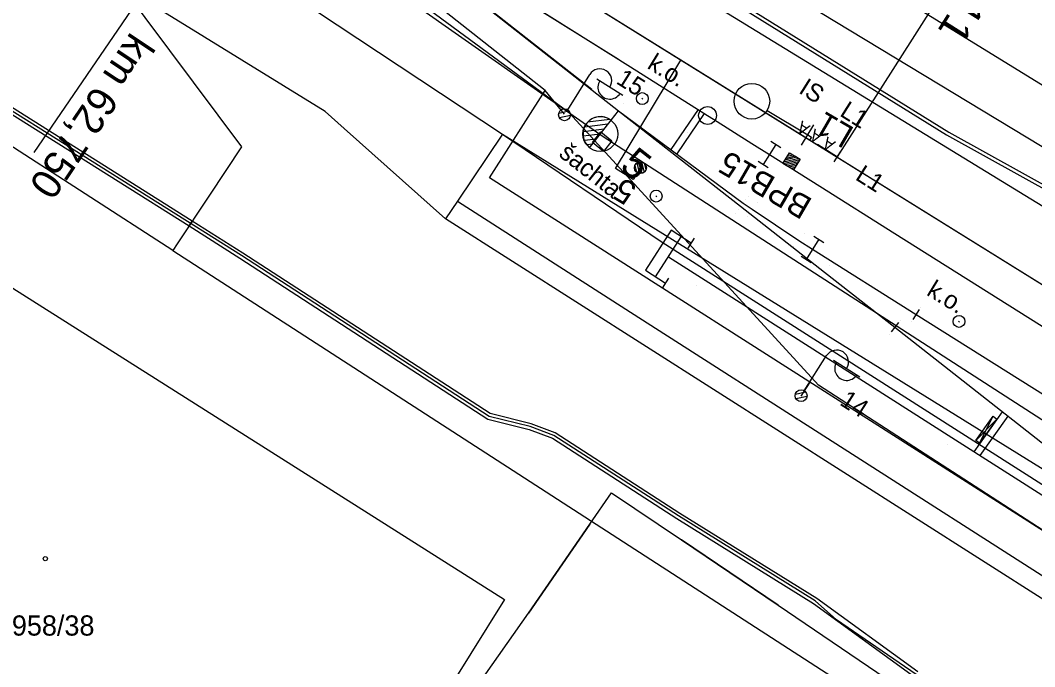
# Model space of a CAD drawing. Extents: x -621168 to -620292, y -1122748 to -1122069.
# Drawn here: x -620861.7 to -620776.3, y -1122403.6 to -1122349.2 of the extents above; entities that cross this region are included whole.
import ezdxf

# ---------------------------------------------------------------- set-up
doc = ezdxf.new("R2010")
doc.units = 0
for name, color, linetype in [('060601_EOV', 7, 'Continuous'), ('060604_ROZVODY_SEE', 7, 'Continuous'), ('CETIN', 7, 'Continuous'), ('HranDP', 7, 'Continuous'), ('Hranice parcel', 7, 'Continuous'), ('itself', 7, 'Continuous'), ('Parcelní čísla', 7, 'Continuous'), ('PS 06-14-01_trasa_sdělovací_nové', 7, 'Continuous'), ('SEE', 7, 'Continuous'), ('SSZT', 7, 'Continuous'), ('SSZT-DK', 7, 'Continuous'), ('UZEMNĚNÍ', 7, 'Continuous'), ('Vnitřní kresba', 7, 'Continuous'), ('Vrstva 1', 7, 'Continuous'), ('Vrstva 10', 7, 'Continuous'), ('Vrstva 15', 7, 'Continuous'), ('Vrstva 2', 7, 'Continuous'), ('Vrstva 25', 7, 'Continuous'), ('Vrstva 27', 7, 'Continuous'), ('Vrstva 3', 7, 'Continuous'), ('Vrstva 47', 7, 'Continuous'), ('Vrstva 6', 7, 'Continuous'), ('Vrstva 62', 7, 'Continuous'), ('Vrstva 7', 7, 'Continuous'), ('Věcná břemena k části', 7, 'Continuous'), ('Značky budov', 7, 'Continuous'), ('ČD-T', 7, 'Continuous')]:
    doc.layers.add(name, color=color, linetype=linetype)

msp = doc.modelspace()

# ---------------------------------------------------------------- linework, layer by layer
at = {"layer": '060601_EOV'}
msp.add_lwpolyline([(-620377.179, -1122637.257), (-620411.557, -1122614.916), (-620424.156, -1122607.087), (-620443.525, -1122595.005), (-620456.111, -1122587.123), (-620447.823, -1122572.959), (-620450.948, -1122571.455), (-620470.592, -1122561.479), (-620499.61, -1122545.574), (-620522.038, -1122531.471), (-620538.89, -1122521.208), (-620599.215, -1122483.216), (-620683.524, -1122429.444), (-620729.121, -1122400.659), (-620738.886, -1122415.694), (-620750.529, -1122408.246), (-620763.558, -1122399.82), (-620784.65, -1122386.386), (-620822.218, -1122362.419), (-620817.53, -1122355.085), (-620826.407, -1122348.082), (-620839.916, -1122337.943), (-620848.842, -1122331.997), (-620848.834, -1122331.986)], dxfattribs=at)
at = {"layer": '060604_ROZVODY_SEE'}
for p, q in [((-620815.893, -1122357.078), (-620817.53, -1122355.085)), ((-620795.983, -1122380.803), (-620795.236, -1122379.632))]:
    msp.add_line(p, q, dxfattribs=at)
msp.add_lwpolyline([(-620443.525, -1122595.005), (-620456.111, -1122587.123), (-620447.823, -1122572.959), (-620450.948, -1122571.455), (-620470.592, -1122561.479), (-620499.61, -1122545.574), (-620522.038, -1122531.471), (-620538.89, -1122521.208), (-620599.215, -1122483.216), (-620683.524, -1122429.444), (-620729.121, -1122400.659), (-620738.886, -1122415.694), (-620750.529, -1122408.246), (-620763.558, -1122399.82), (-620784.65, -1122386.386), (-620822.218, -1122362.419), (-620817.53, -1122355.085), (-620826.407, -1122348.082), (-620839.916, -1122337.943), (-620854.567, -1122328.184), (-620868.06, -1122319.694), (-620885.37, -1122308.815), (-620912.868, -1122291.527), (-620913.325, -1122292.255)], dxfattribs=at)
at = {"layer": 'CETIN'}
for points in [[(-621086.886, -1122186.715), (-621044.703, -1122204.841), (-620975.938, -1122239.692), (-620943.103, -1122258.616), (-620748.436, -1122376.269), (-620484.52, -1122538.147)], [(-620825.92, -1122405.87), (-620824.51, -1122406.99), (-620818.94, -1122399.06), (-620813.77, -1122391.56), (-620811.94, -1122388.94), (-620806.05, -1122392.88), (-620797.93, -1122398.39), (-620788.82, -1122404.57), (-620785.51, -1122405.86), (-620781.04, -1122408.44), (-620779.59, -1122408.85), (-620776.1, -1122410.97), (-620774.86, -1122411.81), (-620766.93, -1122416.76), (-620729.54, -1122440.11), (-620722.4, -1122445), (-620713.88, -1122450.37)], [(-620813.77, -1122391.56), (-620818.94, -1122399.06)], [(-620797.93, -1122398.39), (-620806.05, -1122392.88)]]:
    msp.add_lwpolyline(points, dxfattribs=at)
at = {"layer": 'HranDP'}
msp.add_line((-620856.79, -1122335.14), (-620821.12, -1122358.76), dxfattribs=at)
for points in [[(-620847.72, -1122320.67), (-620838.83, -1122326.12), (-620768.63, -1122369.09), (-620748.53, -1122378.52), (-620702.13, -1122406.7), (-620691.02, -1122413.66), (-620638.48, -1122446.57), (-620552.09, -1122499.2)], [(-620821.12, -1122358.76), (-620741.46, -1122408.09), (-620679.51, -1122447.56), (-620545.92, -1122532.26), (-620521.41, -1122548.27), (-620511.29, -1122557.64)]]:
    msp.add_lwpolyline(points, dxfattribs=at)
at = {"layer": 'Hranice parcel'}
for p, q in [((-620866.03, -1122298.98), (-620688.16, -1122408.5)), ((-620848.87, -1122368.55), (-620933.94, -1122313.6)), ((-620856.79, -1122335.14), (-620821.12, -1122358.76))]:
    msp.add_line(p, q, dxfattribs=at)
for points in [[(-620847.72, -1122320.67), (-620838.83, -1122326.12), (-620768.63, -1122369.09), (-620748.53, -1122378.52), (-620702.13, -1122406.7), (-620691.02, -1122413.66), (-620638.48, -1122446.57), (-620552.09, -1122499.2)], [(-620825.92, -1122365.89), (-620834.44, -1122358.28), (-620836.04, -1122356.85), (-620853.22, -1122346.25)], [(-620853.22, -1122346.25), (-620843.09, -1122359.81), (-620845.8, -1122363.88), (-620848.5, -1122367.99), (-620848.87, -1122368.55)], [(-620929.94, -1122378.34), (-620913.46, -1122352.29), (-620887.98, -1122368.3), (-620877.81, -1122374.71), (-620872.17, -1122365.51), (-620820.94, -1122397.9), (-620826.62, -1122407), (-620821.36, -1122410.31), (-620837.94, -1122436.41), (-620904.18, -1122394.6), (-620929.94, -1122378.34)], [(-620821.12, -1122358.76), (-620824.91, -1122364.39), (-620825.92, -1122365.89)], [(-620821.12, -1122358.76), (-620741.46, -1122408.09), (-620679.51, -1122447.56), (-620545.92, -1122532.26), (-620521.41, -1122548.27), (-620511.29, -1122557.64)], [(-620821.12, -1122358.76), (-620807.67, -1122367.84), (-620645.72, -1122471.03), (-620587.17, -1122509.18), (-620511.29, -1122557.64)], [(-620557.45, -1122536.96), (-620684.91, -1122455.63), (-620825.92, -1122365.89)], [(-620848.87, -1122368.55), (-620781.81, -1122411.87), (-620814.37, -1122462.27), (-620846.855, -1122512.555)]]:
    msp.add_lwpolyline(points, dxfattribs=at)
at = {"layer": 'itself'}
msp.add_lwpolyline([(-620786.306, -1122404.212), (-620792.996, -1122399.612), (-620794.806, -1122398.032), (-620806.306, -1122390.882), (-620816.806, -1122384.122), (-620818.796, -1122383.362), (-620822.246, -1122382.502), (-620843.096, -1122368.972), (-620871.286, -1122351.222)], dxfattribs=at)
at = {"layer": 'PS 06-14-01_trasa_sdělovací_nové'}
msp.add_lwpolyline([(-620756.33, -1122383.523), (-620759.752, -1122381.362), (-620756.353, -1122375.206), (-620764.724, -1122371.2), (-620767.847, -1122376.3), (-620853.066, -1122323.342), (-620895.691, -1122296.632), (-620912.11, -1122286.226), (-620914.885, -1122290.617), (-620964.537, -1122259.534), (-620982.106, -1122249.221), (-620983.24, -1122251.5), (-621017.63, -1122231.729), (-621052.339, -1122216.079), (-621085.519, -1122202.489), (-621084.026, -1122198.756), (-621092.027, -1122195.557)], dxfattribs=at)
at = {"layer": 'SEE'}
msp.add_lwpolyline([(-620377.188, -1122637.273), (-620390.254, -1122629.02), (-620411.934, -1122614.961), (-620423.125, -1122608.012), (-620468.337, -1122579.91), (-620468.337, -1122579.91), (-620460.94, -1122568.103), (-620517.418, -1122533.032), (-620535.001, -1122522.477), (-620545.407, -1122539.454), (-620611.375, -1122497.696), (-620665.569, -1122462.755), (-620686.035, -1122449.829), (-620727.537, -1122423.183), (-620794.508, -1122379.862), (-620815.52, -1122356.954), (-620832.168, -1122344.663), (-620847.808, -1122332.592), (-620908.257, -1122294.686)], dxfattribs=at)
at = {"layer": 'SSZT'}
msp.add_lwpolyline([(-620879.238, -1122313.316), (-620842.993, -1122336.61), (-620835.049, -1122343.251), (-620812.66, -1122358.949), (-620764.902, -1122389.752), (-620688.594, -1122438.969), (-620596.981, -1122496.725), (-620576.744, -1122509.484), (-620506.746, -1122556.123), (-620447.293, -1122593.619), (-620377.761, -1122638.259)], dxfattribs=at)
at = {"layer": 'SSZT-DK'}
msp.add_lwpolyline([(-621084.334, -1122182.327), (-621080.248, -1122184.036), (-621051.504, -1122198.928), (-620999.37, -1122227.003), (-620959.935, -1122250.539), (-620931.349, -1122267.519), (-620900.269, -1122286.467), (-620889.147, -1122293.455), (-620783.743, -1122358.818), (-620712.751, -1122398.176), (-620653.117, -1122435.232), (-620617.363, -1122456.738), (-620574.425, -1122482.604), (-620528.157, -1122511.106), (-620496.311, -1122530.834), (-620515.025, -1122558.813), (-620500.383, -1122568.606), (-620465.393, -1122591.454), (-620452.16, -1122605.021), (-620438.234, -1122615.496), (-620392.309, -1122655.212), (-620389.253, -1122658.022)], dxfattribs=at)
at = {"layer": 'UZEMNĚNÍ'}
for p, q in [((-620815.893, -1122357.078), (-620817.53, -1122355.085)), ((-620795.983, -1122380.803), (-620795.236, -1122379.632))]:
    msp.add_line(p, q, dxfattribs=at)
msp.add_lwpolyline([(-620742.353, -1122414.851), (-620741.729, -1122413.876), (-620750.529, -1122408.246), (-620763.558, -1122399.82), (-620784.65, -1122386.386), (-620822.218, -1122362.419), (-620817.53, -1122355.085), (-620826.407, -1122348.082), (-620838.671, -1122338.878), (-620840.227, -1122340.951)], dxfattribs=at)
at = {"layer": 'Vnitřní kresba'}
for p, q in [((-620824.91, -1122364.39), (-620810.36, -1122373.73)), ((-620810.36, -1122373.73), (-620648.08, -1122477.56))]:
    msp.add_line(p, q, dxfattribs=at)
at = {"layer": 'Vrstva 1'}
for p, q in [((-620806.105, -1122352.525), (-620848.094, -1122326.432)), ((-620811.617, -1122361.655), (-620806.105, -1122352.525))]:
    msp.add_line(p, q, dxfattribs=at)
for points in [[(-620865.133, -1122318.582), (-620858.377, -1122322.838), (-620854.485, -1122325.283), (-620853.208, -1122326.085), (-620851.733, -1122327.008), (-620850.549, -1122327.758), (-620840.578, -1122334.049), (-620833.632, -1122338.433), (-620832.14, -1122339.366), (-620823.776, -1122344.632), (-620817.743, -1122348.457), (-620811.366, -1122352.452)], [(-620853.345, -1122326.031), (-620853.187, -1122326.13), (-620851.644, -1122327.076), (-620843.142, -1122332.434), (-620837.627, -1122335.918), (-620832.116, -1122339.39), (-620828.016, -1122341.966), (-620823.788, -1122344.633), (-620816.971, -1122348.943), (-620810.355, -1122353.089), (-620803.86, -1122357.181), (-620803.36, -1122357.495), (-620800.131, -1122359.525), (-620798.65, -1122360.458), (-620794.421, -1122363.123), (-620788.102, -1122367.105), (-620781.123, -1122371.499), (-620774.168, -1122375.876)], [(-620851.644, -1122327.076), (-620843.142, -1122332.434), (-620837.627, -1122335.918), (-620832.116, -1122339.39), (-620828.016, -1122341.966), (-620823.788, -1122344.633), (-620816.971, -1122348.943), (-620810.355, -1122353.089), (-620803.86, -1122357.181), (-620803.36, -1122357.495), (-620800.131, -1122359.525), (-620798.65, -1122360.458), (-620794.421, -1122363.123), (-620788.102, -1122367.105), (-620781.123, -1122371.499), (-620774.168, -1122375.876), (-620767.514, -1122380.058), (-620763.223, -1122382.761), (-620756.392, -1122387.049), (-620748.87, -1122391.776), (-620741.59, -1122396.353), (-620734.607, -1122400.749), (-620727.792, -1122405.031)], [(-620851.644, -1122327.076), (-620840.376, -1122334.591), (-620831.192, -1122341.263), (-620824.896, -1122346.12), (-620811.348, -1122356.777), (-620800.849, -1122364.554), (-620800.095, -1122365.072), (-620796.174, -1122367.693), (-620795.017, -1122368.443), (-620786.31, -1122373.928), (-620764.415, -1122387.671), (-620747.632, -1122398.188), (-620733.731, -1122406.893), (-620718.349, -1122416.524), (-620703.006, -1122426.145), (-620686.977, -1122436.203), (-620670.849, -1122446.339), (-620652.243, -1122458.025), (-620632.992, -1122470.125), (-620616.992, -1122480.169), (-620599.707, -1122491.044), (-620582.331, -1122501.971), (-620566.971, -1122511.728)], [(-620850.549, -1122327.758), (-620838.472, -1122335.901), (-620831.257, -1122341.177), (-620824.882, -1122346.101), (-620819.561, -1122350.304), (-620813.61, -1122354.966)], [(-620795.273, -1122359.257), (-620795.675, -1122359.007), (-620806.105, -1122352.525)], [(-620811.348, -1122356.777), (-620801.076, -1122364.818), (-620794.028, -1122370.353), (-620788.085, -1122375.002), (-620768.881, -1122390.097), (-620768.433, -1122390.449), (-620761.754, -1122395.699), (-620755.252, -1122400.953), (-620748.862, -1122405.846), (-620748.158, -1122406.325), (-620737.324, -1122413.726), (-620723.134, -1122422.771)], [(-620795.422, -1122358.821), (-620795.117, -1122359.006), (-620795.273, -1122359.257)], [(-620764.724, -1122371.2), (-620767.847, -1122376.3), (-620794.599, -1122359.676), (-620795.273, -1122359.257)], [(-620809.512, -1122361.576), (-620810.11, -1122362.565), (-620811.617, -1122361.655)], [(-620807.154, -1122369.064), (-620804.382, -1122370.836), (-620783.306, -1122384.278), (-620762.208, -1122397.716), (-620749.177, -1122406.143), (-620748.333, -1122406.684), (-620737.324, -1122413.726)]]:
    msp.add_lwpolyline(points, dxfattribs=at)
at = {"layer": 'Vrstva 10'}
msp.add_line((-620844.131, -1122336.244), (-620860.567, -1122360.289), dxfattribs=at)
at = {"layer": 'Vrstva 15'}
for p, q in [((-620808.231, -1122370.749), (-620806.077, -1122367.379)), ((-620805.504, -1122368.339), (-620804.965, -1122367.496)), ((-620807.658, -1122371.709), (-620807.119, -1122370.866))]:
    msp.add_line(p, q, dxfattribs=at)
msp.add_lwpolyline([(-620805.234, -1122367.917), (-620806.919, -1122366.84), (-620809.074, -1122370.211), (-620807.389, -1122371.288)], dxfattribs=at)
at = {"layer": 'Vrstva 2'}
for p, q in [((-620812.074, -1122357.526), (-620813.959, -1122357.755)), ((-620813.787, -1122359.892), (-620811.982, -1122357.587)), ((-620811.982, -1122357.587), (-620811.348, -1122356.777)), ((-620798.847, -1122356.755), (-620795.422, -1122358.821)), ((-620812.569, -1122358.341), (-620814.332, -1122358.556)), ((-620812.242, -1122357.924), (-620814.226, -1122358.165)), ((-620795.938, -1122359.677), (-620794.905, -1122357.964)), ((-620812.897, -1122358.759), (-620814.33, -1122358.933)), ((-620813.223, -1122359.176), (-620814.231, -1122359.299)), ((-620813.551, -1122359.594), (-620814.024, -1122359.652)), ((-620796.102, -1122360.913), (-620797.458, -1122361.249)), ((-620796.175, -1122360.796), (-620797.448, -1122361.111)), ((-620796.334, -1122360.7), (-620797.352, -1122360.952)), ((-620796.493, -1122360.604), (-620797.256, -1122360.793)), ((-620796.652, -1122360.509), (-620797.16, -1122360.634)), ((-620796.811, -1122360.413), (-620797.064, -1122360.476)), ((-620809.973, -1122361.382), (-620809.829, -1122361.961)), ((-620809.816, -1122361.18), (-620809.597, -1122362.068)), ((-620809.632, -1122361.091), (-620809.393, -1122362.059)), ((-620809.428, -1122361.085), (-620809.209, -1122361.971)), ((-620809.196, -1122361.191), (-620809.053, -1122361.768)), ((-620796.198, -1122361.072), (-620797.299, -1122361.345)), ((-620796.294, -1122361.231), (-620797.14, -1122361.441)), ((-620796.39, -1122361.39), (-620796.981, -1122361.536)), ((-620796.486, -1122361.549), (-620796.822, -1122361.632)), ((-620796.582, -1122361.708), (-620796.663, -1122361.728)), ((-620786.044, -1122373.505), (-620786.576, -1122374.351)), ((-620787.776, -1122374.609), (-620788.394, -1122375.395))]:
    msp.add_line(p, q, dxfattribs=at)
for points in [[(-620811.348, -1122356.777), (-620800.849, -1122364.554), (-620800.095, -1122365.072), (-620796.174, -1122367.693), (-620795.017, -1122368.443), (-620786.31, -1122373.928)], [(-620811.348, -1122356.777), (-620801.076, -1122364.818), (-620794.028, -1122370.353), (-620788.085, -1122375.002)]]:
    msp.add_lwpolyline(points, dxfattribs=at)
msp.add_lwpolyline([(-620796.612, -1122361.759), (-620797.511, -1122361.216), (-620796.969, -1122360.317), (-620796.07, -1122360.86)], close=True, dxfattribs=at)
msp.add_lwpolyline([(-620796.612, -1122361.759), (-620797.511, -1122361.216), (-620796.969, -1122360.317), (-620796.07, -1122360.86)], close=True, dxfattribs=at)
for centre, radius in [((-620800.131, -1122355.98), 1.5), ((-620812.884, -1122358.74), 1.464), ((-620809.512, -1122361.576), 0.5)]:
    msp.add_circle(centre, radius, dxfattribs=at)
msp.add_arc((-620812.884, -1122358.74), 1.463, 51.96502, 231.92587, dxfattribs=at)
at = {"layer": 'Vrstva 25'}
for p, q in [((-620815.635, -1122356.695), (-620813.777, -1122353.73)), ((-620813.184, -1122354.101), (-620810.981, -1122355.482)), ((-620816.384, -1122356.989), (-620815.526, -1122356.792)), ((-620816.336, -1122357.362), (-620815.402, -1122357.148)), ((-620795.717, -1122380.341), (-620793.836, -1122377.39)), ((-620793.246, -1122377.766), (-620791.053, -1122379.163)), ((-620796.468, -1122380.629), (-620795.609, -1122380.439)), ((-620796.422, -1122381.003), (-620795.488, -1122380.796))]:
    msp.add_line(p, q, dxfattribs=at)
for centre in [(-620815.901, -1122357.119), (-620795.986, -1122380.763)]:
    msp.add_circle(centre, 0.5, dxfattribs=at)
for centre, start, end in [((-620812.93, -1122354.261), 327.92616, 147.92616), ((-620812.089, -1122354.802), 147.22359, 328.62874), ((-620792.993, -1122377.927), 327.49225, 147.49225), ((-620792.156, -1122378.475), 146.78967, 328.19482)]:
    msp.add_arc(centre, 1, start, end, dxfattribs=at)
at = {"layer": 'Vrstva 27'}
for p, q in [((-620809.397, -1122355.73), (-620809.311, -1122355.782)), ((-620782.736, -1122374.485), (-620782.65, -1122374.537))]:
    msp.add_line(p, q, dxfattribs=at)
for centre in [(-620809.354, -1122355.756), (-620782.693, -1122374.511)]:
    msp.add_circle(centre, 0.5, dxfattribs=at)
at = {"layer": 'Vrstva 3'}
for p, q in [((-620798.117, -1122359.612), (-620799.183, -1122361.304)), ((-620798.117, -1122359.612), (-620799.183, -1122361.304)), ((-620798.54, -1122359.345), (-620797.694, -1122359.878)), ((-620798.54, -1122359.345), (-620797.694, -1122359.879)), ((-620799.606, -1122361.037), (-620798.76, -1122361.571)), ((-620799.606, -1122361.038), (-620798.76, -1122361.571)), ((-620794.484, -1122367.597), (-620795.55, -1122369.289)), ((-620794.907, -1122367.33), (-620794.061, -1122367.863)), ((-620795.973, -1122369.023), (-620795.127, -1122369.556))]:
    msp.add_line(p, q, dxfattribs=at)
at = {"layer": 'Vrstva 47'}
msp.add_lwpolyline([(-620813.538, -1122359.464), (-620812.851, -1122358.551), (-620811.904, -1122359.301), (-620812.62, -1122360.204), (-620813.538, -1122359.464)], dxfattribs=at)
at = {"layer": 'Vrstva 6'}
for p, q in [((-620792.925, -1122360.656), (-620777.003, -1122335.648)), ((-620794.6, -1122359.6), (-620792.925, -1122360.656)), ((-620794.6, -1122359.6), (-620792.925, -1122360.656)), ((-620793.192, -1122361.079), (-620792.658, -1122360.233)), ((-620793.192, -1122361.079), (-620792.658, -1122360.233))]:
    msp.add_line(p, q, dxfattribs=at)
at = {"layer": 'Vrstva 62'}
for p, q in [((-620810.907, -1122356.198), (-620810.907, -1122356.198)), ((-620811.788, -1122357.355), (-620811.788, -1122357.355)), ((-620800.637, -1122364.243), (-620800.637, -1122364.243)), ((-620800.408, -1122364.001), (-620800.408, -1122364.001)), ((-620801.29, -1122365.107), (-620801.29, -1122365.107)), ((-620799.679, -1122364.494), (-620799.679, -1122364.494)), ((-620801.514, -1122365.393), (-620801.514, -1122365.393)), ((-620800.511, -1122365.651), (-620800.511, -1122365.651)), ((-620795.725, -1122367.141), (-620795.725, -1122367.141)), ((-620806.771, -1122368.468), (-620806.771, -1122368.468)), ((-620796.623, -1122368.246), (-620796.623, -1122368.246)), ((-620794.609, -1122367.871), (-620794.609, -1122367.871)), ((-620795.426, -1122369.016), (-620795.426, -1122369.016)), ((-620807.538, -1122369.661), (-620807.538, -1122369.661)), ((-620804.006, -1122370.225), (-620804.006, -1122370.225)), ((-620793.614, -1122369.769), (-620793.614, -1122369.769)), ((-620794.442, -1122370.937), (-620794.442, -1122370.937)), ((-620804.758, -1122371.448), (-620804.758, -1122371.448)), ((-620785.935, -1122373.327), (-620785.935, -1122373.327)), ((-620787.647, -1122374.431), (-620787.647, -1122374.431)), ((-620786.685, -1122374.529), (-620786.685, -1122374.529)), ((-620788.522, -1122375.574), (-620788.522, -1122375.574)), ((-620782.922, -1122383.661), (-620782.922, -1122383.661)), ((-620783.69, -1122384.896), (-620783.69, -1122384.896))]:
    msp.add_line(p, q, dxfattribs=at)
at = {"layer": 'Vrstva 7'}
for p, q in [((-620804.647, -1122356.685), (-620806.942, -1122360.04)), ((-620804.139, -1122357.005), (-620806.46, -1122360.398)), ((-620805.585, -1122358.587), (-620805.585, -1122358.587)), ((-620808.226, -1122363.939), (-620808.142, -1122363.993)), ((-620808.226, -1122363.939), (-620808.142, -1122363.993)), ((-620781.416, -1122385.482), (-620779.032, -1122382.118)), ((-620779.497, -1122382.73), (-620781.281, -1122384.526)), ((-620780.91, -1122385.804), (-620778.56, -1122382.489)), ((-620780.045, -1122384.066), (-620780.045, -1122384.066))]:
    msp.add_line(p, q, dxfattribs=at)
msp.add_lwpolyline([(-620780.956, -1122384.76), (-620779.822, -1122382.496), (-620779.497, -1122382.73), (-620780.956, -1122384.76), (-620781.281, -1122384.526), (-620779.822, -1122382.496)], dxfattribs=at)
for centre, radius in [((-620803.86, -1122357.181), 0.75), ((-620803.86, -1122357.181), 0.75), ((-620808.184, -1122363.966), 0.5), ((-620808.184, -1122363.966), 0.5)]:
    msp.add_circle(centre, radius, dxfattribs=at)
at = {"layer": 'Věcná břemena k části'}
msp.add_lwpolyline([(-620940.9, -1122305.27), (-620939.94, -1122306.28), (-620932.68, -1122311.73), (-620917.76, -1122321.94), (-620897.11, -1122334.91), (-620871.42, -1122351.43), (-620847.51, -1122366.48), (-620847.24, -1122366.07), (-620871.16, -1122351.01), (-620896.85, -1122334.49), (-620917.48, -1122321.52), (-620932.38, -1122311.33), (-620939.6, -1122305.9), (-620940.4, -1122305.07), (-620940.78, -1122305.04)], close=True, dxfattribs=at)
msp.add_lwpolyline([(-620786.17, -1122404), (-620794.67, -1122397.82), (-620806.18, -1122390.67), (-620816.7, -1122383.9), (-620818.72, -1122383.12), (-620822.15, -1122382.27), (-620842.97, -1122368.76), (-620847.24, -1122366.07), (-620847.51, -1122366.48), (-620843.23, -1122369.18), (-620822.35, -1122382.73), (-620818.88, -1122383.6), (-620816.92, -1122384.34), (-620806.44, -1122391.09), (-620794.95, -1122398.24), (-620786.45, -1122404.42)], dxfattribs=at)
at = {"layer": 'Značky budov'}
msp.add_circle((-620859.607, -1122394.469), 0.175, dxfattribs=at)
at = {"layer": 'ČD-T'}
msp.add_lwpolyline([(-621084.188, -1122182.075), (-621080.06, -1122183.802), (-621051.317, -1122198.693), (-620999.183, -1122226.768), (-620959.747, -1122250.305), (-620931.162, -1122267.284), (-620900.082, -1122286.233), (-620888.96, -1122293.22), (-620783.556, -1122358.583), (-620712.564, -1122397.941), (-620652.93, -1122434.998), (-620617.176, -1122456.504), (-620574.237, -1122482.37), (-620527.969, -1122510.872), (-620481.077, -1122540.08), (-620497.003, -1122565.384), (-620499.265, -1122568.979), (-620465.206, -1122591.22), (-620451.973, -1122604.786), (-620438.046, -1122615.261), (-620392.122, -1122654.977), (-620389.098, -1122657.757)], dxfattribs=at)

# ---------------------------------------------------------------- texts
at = {"layer": 'Parcelní čísla'}
msp.add_text('2958/38', height=1.7, dxfattribs=at).set_placement((-620863.688, -1122400.95))
at = {"layer": 'Vrstva 10'}
msp.add_text('km 62,750', height=2.5, rotation=236.29937, dxfattribs=at).set_placement((-620852.398, -1122350.056))
at = {"layer": 'Vrstva 2'}
msp.add_text('5', height=2.5, rotation=321.94589, dxfattribs=at).set_placement((-620811.354, -1122361.655))
at = {"layer": 'Vrstva 25'}
for s, rotation, p in [('15', 327.92616, (-620811.637, -1122354.436)), ('14', 327.49225, (-620792.822, -1122381.476))]:
    msp.add_text(s, height=1.5, rotation=rotation, dxfattribs=at).set_placement(p)
at = {"layer": 'Vrstva 27'}
for p in [(-620809.024, -1122353.158), (-620785.504, -1122372.238)]:
    msp.add_text('k.o.', height=1.5, rotation=328.4879, dxfattribs=at).set_placement(p)
at = {"layer": 'Vrstva 3'}
for s, height, rotation, p in [('IS', 1.5, 327.7899, (-620796.269, -1122355.229)), ('L1', 2, 149.82357, (-620791.406, -1122358.283)), ('BPB15', 2, 149.82357, (-620794.924, -1122364.273)), ('5', 2, 148.87857, (-620809.692, -1122363.108))]:
    msp.add_text(s, height=height, rotation=rotation, dxfattribs=at).set_placement(p)
at = {"layer": 'Vrstva 47'}
msp.add_text('šachta', height=1.5, rotation=321.62167, dxfattribs=at).set_placement((-620816.466, -1122360.548))
at = {"layer": 'Vrstva 6'}
for s, height, rotation, p in [('km 62,811', 2.5, 237.78239, (-620776.215, -1122336.799)), ('L1', 1.5, 327.78239, (-620792.815, -1122357.156)), ('  A A A ', 1, 147.78239, (-620792.392, -1122359.81)), ('  A A ', 1, 147.78239, (-620792.392, -1122359.81)), ('L1', 1.5, 327.78239, (-620791.506, -1122362.527))]:
    msp.add_text(s, height=height, rotation=rotation, dxfattribs=at).set_placement(p)

doc.saveas('drawing.dxf')
